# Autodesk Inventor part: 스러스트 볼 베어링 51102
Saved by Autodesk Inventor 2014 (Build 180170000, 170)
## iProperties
Created: 2025-09
Part Number: 스러스트 볼 베어링 51102
Material: 일반
Document SubType Name: Modeling
Designer: dg
Density: 1 g/cm^3
Appearance: 기본값
Author: dg
Author: jhkim
Description: 롤링 베어링 - 플랫 뒷면이 있는 스러스트 볼 베어링
Creation Date: 2025-09-02
Sending System: Autodesk Inventor 2026
Preprocessor: ST-DEVELOPER v20.1
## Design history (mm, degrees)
node "스러스트 볼 베어링 511021"
body "Solid1"
node "Solid1_1"
node "Solid1_2"
node "Solid1_3"
node "Solid1_4"
node "Solid1_5"
node "Solid1_6"
node "Solid1_7"
node "Solid1_8"
node "Solid1_9"
node "Solid1_10"
node "기준1"
node "기준2"
node "기준3"
node "기준4"
node "기준5"
node "기준6"
node "기준7"
node "기준8"
node "기준9"
node "기준10"
node "기준11"
